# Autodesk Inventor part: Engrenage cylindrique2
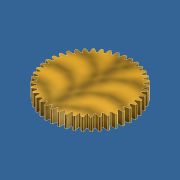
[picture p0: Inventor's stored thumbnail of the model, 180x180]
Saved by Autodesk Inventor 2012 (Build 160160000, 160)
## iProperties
Created: 2011-10
Part Number: Engrenage cylindrique2
Material: Acier
Document SubType Name: Modeling
Designer: Laur
Density: 1 g/cm^3
CustomPartVersion: 1
Author: Laur
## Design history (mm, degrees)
sketch "Sketch1"
  geometry: C1 r 6.63 at (0, 0)
  constraints: 1 centre point
  dimensions: "d0" = 13.26 diameter of C1 (= da_da)
extrude "Extrusion1" new body sketch "Sketch1" distance "d1" = 2 (= da_b); taper "d2" = 0 deg
workplane "Work Plane2"
sketch "Sketch2"
  geometry: C1 r 6.63 at (0, 0) reference; C2 r 6.45 at (0, 0)
  constraints: 1 centre point, 1 coincident
  dimensions: "d3" = 12.9 diameter of C2 (= da_dw)
extrude_surface "ExtrusionSrf1" sketch "Sketch2" dims "d4" = 10, "d5" = 0
workplane "Work Plane8"
workplane "Work Plane9"
feature "Engrenage cylindrique" dims "da_b" = 2, "da_d" = 12.9, "da_aw" = 7.95, "da_da" = 13.26, "da_df" = 11.91, "da_dw" = 12.9, angle "da_beta" = 0 deg, "da_lefttooth" = 0, "da_righttooth" = 0
sketch "Esquisse3"
  geometry: C1 r 1.5 at (0, 0) reference
extrude "Extrusion2" cut sketch "Esquisse3" stored distance "d49" = 10; taper "d50" = 0 deg
node "Solide1"
node "Corps solides"
node "Corps surfaciques"
body "Srf1"
node "Référence1"
other parameters: "d16" = 7.95 (= da_aw), "d17" = 0, "d34" = 0.7306 (computed from da_z), "d39" = 0, "d41" = 0, "d43" = 7.95 (= da_aw), "d46" = 7.95 (= da_aw), "d47" = 0, "d48" = 0
